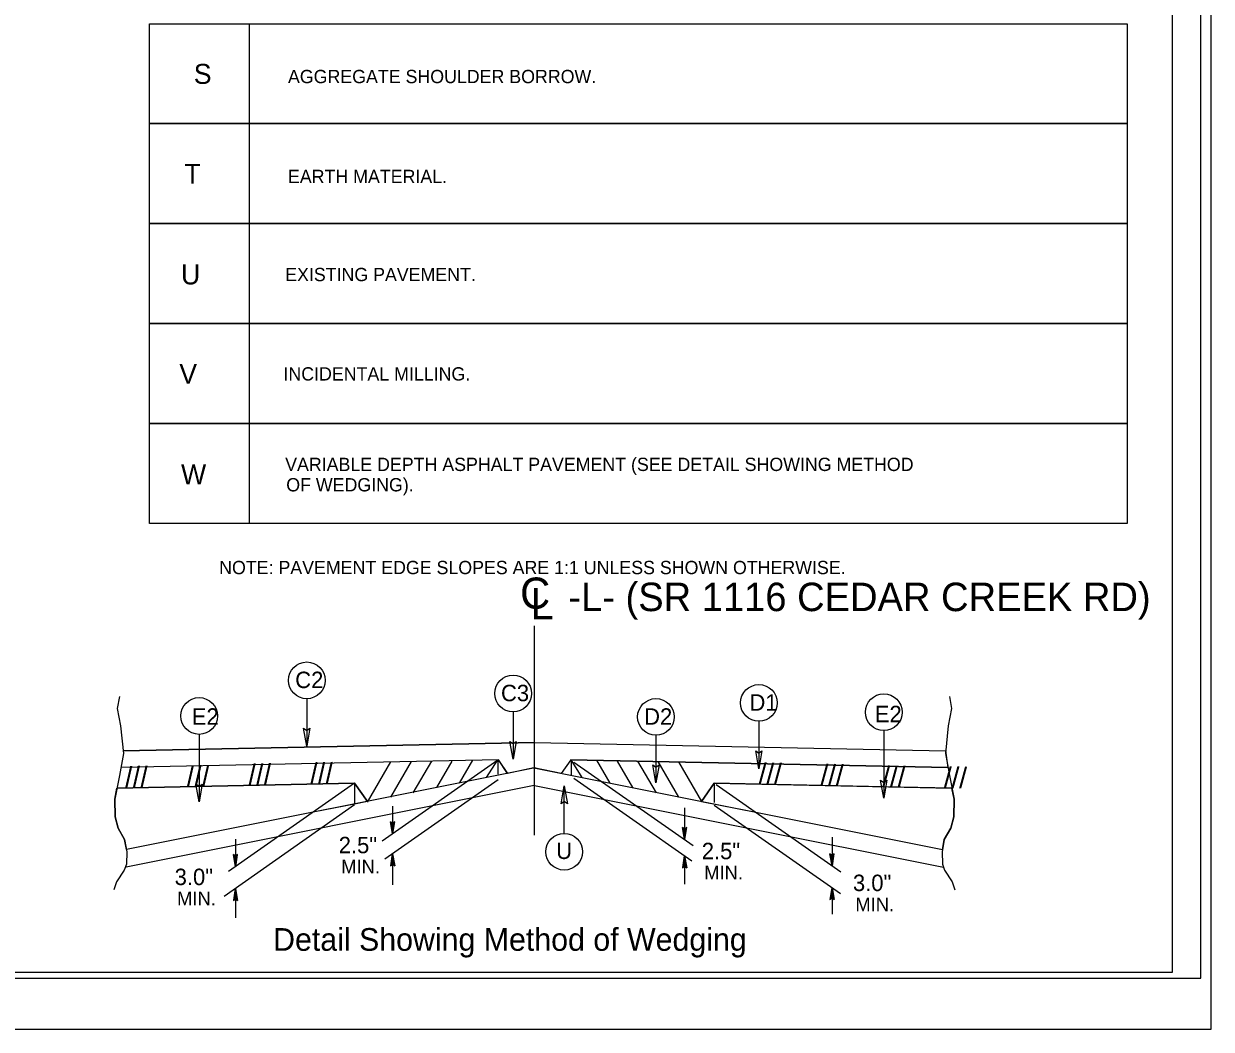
# Model space of a CAD drawing. Extents: x 573732 to 574187, y -53389 to -53257.
# Drawn here: x 573921.8 to 573984.3, y -53388.9 to -53336 of the extents above; entities that cross this region are included whole.
import ezdxf

# ---------------------------------------------------------------- set-up
doc = ezdxf.new("R2010")
doc.units = 0
for name, color, linetype in [('Old_Level_1', 7, 'Continuous'), ('Old_Level_19', 7, 'Continuous'), ('Old_Level_21', 7, 'Continuous'), ('Sheet Cutting Line CELL', 7, 'Continuous'), ('Sheet Plot Border Inside CELL', 7, 'Continuous'), ('Sheet Plot Border Outside CELL', 7, 'Continuous'), ('Sheet Typical CELL', 7, 'Continuous'), ('Typical Detail Wedge2 CELL', 7, 'Continuous'), ('Typical ID Circle CELL', 7, 'Continuous'), ('Typical Terminator CELL', 7, 'Continuous'), ('Typical Text Centerline CELL', 7, 'Continuous'), ('Typical Text General CELL', 7, 'Continuous'), ('Typical Text ID Circle CELL', 7, 'Continuous')]:
    doc.layers.add(name, color=color, linetype=linetype)

# ---------------------------------------------------------------- blocks, each defined once
blk = doc.blocks.new('CENTERLINE TEXT CL')
at = {"layer": 'Typical Text Centerline CELL'}
blk.add_text('C', height=1.64, dxfattribs=at).set_placement((-0.546, -0.261))
blk.add_text('L', height=1.641, rotation=359.9469, dxfattribs=at).set_placement((-0.001, -0.821))
blk = doc.blocks.new('TERMINATOR')
at = {"layer": 'Typical Terminator CELL'}
blk.add_lwpolyline([(-0.469, 0.081), (0, 0), (-0.471, -0.083), (-0.411, 0)], close=True, dxfattribs=at)

msp = doc.modelspace()

# ---------------------------------------------------------------- linework, layer by layer
at = {"layer": 'Old_Level_1'}
for p, q in [((573928.578, -53362.324), (573928.578, -53362.324)), ((573948.672, -53378.727), (573948.672, -53367.698)), ((573948.672, -53378.727), (573948.672, -53371.194))]:
    msp.add_line(p, q, dxfattribs=at)
at = {"layer": 'Old_Level_19'}
for points in [[(573933.675, -53341.256), (573928.412, -53341.256), (573928.412, -53335.994), (573979.867, -53335.994), (573979.867, -53341.256), (573933.675, -53341.256), (573933.675, -53335.994)], [(573933.675, -53346.518), (573928.412, -53346.518), (573928.412, -53341.256), (573979.867, -53341.256), (573979.867, -53346.518), (573933.675, -53346.518), (573933.675, -53341.256)], [(573933.675, -53351.781), (573928.412, -53351.781), (573928.412, -53346.518), (573979.867, -53346.518), (573979.867, -53351.781), (573933.675, -53351.781), (573933.675, -53346.518)], [(573933.675, -53357.043), (573928.412, -53357.043), (573928.412, -53351.781), (573979.867, -53351.781), (573979.867, -53357.043), (573933.675, -53357.043), (573933.675, -53351.781)], [(573933.675, -53362.305), (573928.412, -53362.305), (573928.412, -53357.043), (573979.868, -53357.043), (573979.868, -53362.305), (573933.675, -53362.305), (573933.675, -53357.043)]]:
    msp.add_lwpolyline(points, dxfattribs=at)
at = {"layer": 'Sheet Cutting Line CELL'}
msp.add_line((573782.222, -53388.948), (573984.302, -53388.948), dxfattribs=at)
at = {"layer": 'Sheet Plot Border Inside CELL'}
msp.add_lwpolyline([(573983.762, -53259.642), (573783.782, -53259.642), (573783.782, -53386.254), (573983.762, -53386.254)], close=True, dxfattribs=at)
at = {"layer": 'Sheet Plot Border Outside CELL'}
msp.add_lwpolyline([(573984.302, -53256.948), (573782.222, -53256.948), (573782.222, -53388.948), (573984.302, -53388.948)], close=True, dxfattribs=at)
at = {"layer": 'Sheet Typical CELL'}
msp.add_lwpolyline([(573982.262, -53259.948), (573802.262, -53259.948), (573802.262, -53385.948), (573982.262, -53385.948)], close=True, dxfattribs=at)
at = {"layer": 'Typical Detail Wedge2 CELL'}
for p, q in [((573948.671, -53373.854), (573927.027, -53374.287)), ((573927.027, -53374.287), (573948.671, -53373.854)), ((573948.671, -53373.854), (573970.317, -53374.287)), ((573948.673, -53373.854), (573970.317, -53374.287)), ((573970.317, -53374.287), (573970.441, -53375.156)), ((573946.772, -53374.759), (573926.904, -53375.156)), ((573946.772, -53374.759), (573926.904, -53375.156)), ((573941.096, -53374.873), (573939.866, -53376.981)), ((573946.748, -53374.775), (573940.65, -53379.046)), ((573942.176, -53374.851), (573941.087, -53376.72)), ((573943.245, -53374.83), (573942.268, -53376.505)), ((573944.322, -53374.832), (573943.512, -53376.219)), ((573945.409, -53374.777), (573944.703, -53375.987)), ((573946.157, -53375.685), (573946.745, -53374.767)), ((573946.745, -53374.767), (573946.745, -53375.521)), ((573947.259, -53375.472), (573946.772, -53374.759)), ((573946.772, -53374.782), (573947.259, -53375.472)), ((573950.586, -53374.759), (573950.084, -53375.472)), ((573950.586, -53374.759), (573950.084, -53375.472)), ((573950.554, -53374.775), (573950.585, -53374.777)), ((573950.586, -53374.759), (573970.441, -53375.156)), ((573970.441, -53375.156), (573950.586, -53374.759)), ((573951.186, -53375.685), (573950.599, -53374.767)), ((573950.599, -53374.767), (573950.599, -53375.598)), ((573950.752, -53374.875), (573957.035, -53379.275)), ((573951.934, -53374.777), (573952.641, -53375.987)), ((573953.02, -53374.832), (573953.83, -53376.219)), ((573954.098, -53374.83), (573955.076, -53376.505)), ((573955.167, -53374.851), (573956.256, -53376.72)), ((573956.249, -53374.873), (573957.46, -53376.95)), ((573948.704, -53375.185), (573927.189, -53379.489)), ((573948.639, -53375.185), (573947.259, -53375.472)), ((573948.639, -53375.185), (573970.154, -53379.489)), ((573950.084, -53375.472), (573948.639, -53375.185)), ((573939.203, -53375.996), (573926.693, -53376.246)), ((573926.693, -53376.246), (573939.203, -53375.996)), ((573948.663, -53376.111), (573927.182, -53380.408)), ((573939.203, -53375.996), (573932.56, -53380.647)), ((573939.883, -53376.952), (573939.203, -53375.996)), ((573939.203, -53375.996), (573939.203, -53377.087)), ((573939.203, -53375.996), (573939.882, -53376.95)), ((573946.762, -53375.819), (573940.794, -53379.997)), ((573948.68, -53376.111), (573970.211, -53380.418)), ((573950.743, -53375.73), (573956.965, -53380.086)), ((573958.14, -53375.996), (573957.46, -53376.95)), ((573957.461, -53376.95), (573958.14, -53375.996)), ((573958.14, -53375.996), (573970.651, -53376.246)), ((573958.14, -53375.996), (573958.14, -53377.01)), ((573967.062, -53376.175), (573958.14, -53375.996)), ((573958.241, -53376.066), (573964.793, -53380.655)), ((573970.651, -53376.246), (573967.062, -53376.175)), ((573939.197, -53377.122), (573932.33, -53381.954)), ((573939.203, -53377.086), (573937.024, -53377.522)), ((573939.882, -53376.95), (573939.203, -53377.086)), ((573941.205, -53377.206), (573941.205, -53378.657)), ((573956.576, -53377.29), (573956.576, -53378.953)), ((573957.46, -53376.95), (573960.319, -53377.522)), ((573958.14, -53377.142), (573964.782, -53381.795)), ((573937.024, -53377.522), (573927.189, -53379.489)), ((573941.205, -53378.657), (573941.093, -53378.021)), ((573941.205, -53378.104), (573941.093, -53378.021)), ((573941.205, -53378.657), (573941.109, -53378.033)), ((573941.125, -53378.045), (573941.205, -53378.657)), ((573941.205, -53378.657), (573941.14, -53378.056)), ((573941.157, -53378.068), (573941.205, -53378.657)), ((573941.205, -53378.657), (573941.173, -53378.08)), ((573941.189, -53378.092), (573941.205, -53378.657)), ((573941.205, -53378.657), (573941.318, -53378.021)), ((573941.318, -53378.021), (573941.205, -53378.104)), ((573941.302, -53378.033), (573941.205, -53378.657)), ((573941.205, -53378.657), (573941.284, -53378.045)), ((573941.269, -53378.056), (573941.205, -53378.657)), ((573941.205, -53378.657), (573941.253, -53378.068)), ((573941.237, -53378.08), (573941.205, -53378.657)), ((573941.205, -53378.657), (573941.221, -53378.092)), ((573941.205, -53378.104), (573941.205, -53378.657)), ((573960.319, -53377.522), (573970.154, -53379.489)), ((573956.576, -53378.953), (573956.463, -53378.316)), ((573956.576, -53378.399), (573956.463, -53378.316)), ((573956.576, -53378.953), (573956.479, -53378.328)), ((573956.495, -53378.34), (573956.576, -53378.953)), ((573956.576, -53378.953), (573956.511, -53378.352)), ((573956.527, -53378.364), (573956.576, -53378.953)), ((573956.576, -53378.953), (573956.543, -53378.375)), ((573956.559, -53378.387), (573956.576, -53378.953)), ((573956.576, -53378.953), (573956.688, -53378.316)), ((573956.688, -53378.316), (573956.576, -53378.399)), ((573956.671, -53378.328), (573956.576, -53378.953)), ((573956.576, -53378.953), (573956.655, -53378.34)), ((573956.639, -53378.352), (573956.576, -53378.953)), ((573956.576, -53378.953), (573956.623, -53378.364)), ((573956.607, -53378.375), (573956.576, -53378.953)), ((573956.576, -53378.953), (573956.591, -53378.387)), ((573956.576, -53378.399), (573956.576, -53378.953)), ((573932.934, -53378.94), (573932.934, -53380.386)), ((573964.342, -53378.835), (573964.342, -53380.339)), ((573932.934, -53380.386), (573932.821, -53379.75)), ((573932.934, -53379.832), (573932.821, -53379.75)), ((573932.934, -53380.386), (573932.837, -53379.761)), ((573932.855, -53379.774), (573932.934, -53380.386)), ((573932.934, -53380.386), (573932.871, -53379.785)), ((573932.887, -53379.796), (573932.934, -53380.386)), ((573932.934, -53380.386), (573932.902, -53379.808)), ((573932.918, -53379.82), (573932.934, -53380.386)), ((573932.934, -53380.386), (573933.047, -53379.75)), ((573933.047, -53379.75), (573932.934, -53379.832)), ((573933.031, -53379.761), (573932.934, -53380.386)), ((573932.934, -53380.386), (573933.015, -53379.774)), ((573932.999, -53379.785), (573932.934, -53380.386)), ((573932.934, -53380.386), (573932.982, -53379.796)), ((573932.967, -53379.808), (573932.934, -53380.386)), ((573932.934, -53380.386), (573932.95, -53379.82)), ((573932.934, -53379.832), (573932.934, -53380.386)), ((573941.205, -53379.71), (573941.093, -53380.347)), ((573941.109, -53380.334), (573941.205, -53379.71)), ((573941.205, -53379.71), (573941.125, -53380.323)), ((573941.14, -53380.31), (573941.205, -53379.71)), ((573941.205, -53379.71), (573941.157, -53380.299)), ((573941.173, -53380.288), (573941.205, -53379.71)), ((573941.205, -53379.71), (573941.189, -53380.276)), ((573941.205, -53379.71), (573941.205, -53381.344)), ((573941.205, -53379.71), (573941.318, -53380.347)), ((573941.205, -53380.264), (573941.205, -53379.71)), ((573941.221, -53380.276), (573941.205, -53379.71)), ((573941.205, -53379.71), (573941.237, -53380.288)), ((573941.253, -53380.299), (573941.205, -53379.71)), ((573941.205, -53379.71), (573941.269, -53380.31)), ((573941.284, -53380.323), (573941.205, -53379.71)), ((573941.205, -53379.71), (573941.302, -53380.334)), ((573956.576, -53379.813), (573956.463, -53380.45)), ((573956.479, -53380.437), (573956.576, -53379.813)), ((573956.576, -53379.813), (573956.495, -53380.426)), ((573956.511, -53380.413), (573956.576, -53379.813)), ((573956.576, -53379.813), (573956.527, -53380.402)), ((573956.543, -53380.391), (573956.576, -53379.813)), ((573956.576, -53379.813), (573956.559, -53380.379)), ((573956.576, -53379.813), (573956.576, -53381.301)), ((573956.576, -53379.813), (573956.688, -53380.45)), ((573956.576, -53380.367), (573956.576, -53379.813)), ((573956.591, -53380.379), (573956.576, -53379.813)), ((573956.576, -53379.813), (573956.607, -53380.391)), ((573956.623, -53380.402), (573956.576, -53379.813)), ((573956.576, -53379.813), (573956.639, -53380.413)), ((573956.655, -53380.426), (573956.576, -53379.813)), ((573956.576, -53379.813), (573956.671, -53380.437)), ((573964.342, -53380.339), (573964.23, -53379.703)), ((573964.342, -53379.785), (573964.23, -53379.703)), ((573964.342, -53380.339), (573964.246, -53379.715)), ((573964.262, -53379.726), (573964.342, -53380.339)), ((573964.342, -53380.339), (573964.278, -53379.737)), ((573964.294, -53379.75), (573964.342, -53380.339)), ((573964.342, -53380.339), (573964.31, -53379.761)), ((573964.326, -53379.774), (573964.342, -53380.339)), ((573964.342, -53380.339), (573964.455, -53379.703)), ((573964.455, -53379.703), (573964.342, -53379.785)), ((573964.438, -53379.715), (573964.342, -53380.339)), ((573964.342, -53380.339), (573964.422, -53379.726)), ((573964.406, -53379.737), (573964.342, -53380.339)), ((573964.342, -53380.339), (573964.39, -53379.75)), ((573964.374, -53379.761), (573964.342, -53380.339)), ((573964.342, -53380.339), (573964.358, -53379.774)), ((573964.342, -53379.785), (573964.342, -53380.339)), ((573941.093, -53380.347), (573941.205, -53380.264)), ((573941.205, -53380.264), (573941.318, -53380.347)), ((573956.463, -53380.45), (573956.576, -53380.367)), ((573956.576, -53380.367), (573956.688, -53380.45)), ((573932.934, -53381.531), (573932.821, -53382.167)), ((573932.839, -53382.155), (573932.934, -53381.531)), ((573932.934, -53381.531), (573932.855, -53382.143)), ((573932.871, -53382.131), (573932.934, -53381.531)), ((573932.934, -53381.531), (573932.887, -53382.119)), ((573932.902, -53382.108), (573932.934, -53381.531)), ((573932.934, -53381.531), (573932.918, -53382.097)), ((573932.934, -53381.531), (573932.934, -53383.077)), ((573932.934, -53381.531), (573933.047, -53382.167)), ((573932.934, -53382.084), (573932.934, -53381.531)), ((573932.95, -53382.097), (573932.934, -53381.531)), ((573932.934, -53381.531), (573932.967, -53382.108)), ((573932.983, -53382.119), (573932.934, -53381.531)), ((573932.934, -53381.531), (573932.999, -53382.131)), ((573933.015, -53382.143), (573932.934, -53381.531)), ((573932.934, -53381.531), (573933.031, -53382.155)), ((573964.342, -53381.486), (573964.23, -53382.123)), ((573964.246, -53382.111), (573964.342, -53381.486)), ((573964.342, -53381.486), (573964.262, -53382.099)), ((573964.278, -53382.087), (573964.342, -53381.486)), ((573964.342, -53381.486), (573964.294, -53382.075)), ((573964.31, -53382.063), (573964.342, -53381.486)), ((573964.342, -53381.486), (573964.326, -53382.052)), ((573964.342, -53381.486), (573964.342, -53382.883)), ((573964.342, -53381.486), (573964.455, -53382.123)), ((573964.342, -53382.039), (573964.342, -53381.486)), ((573964.358, -53382.052), (573964.342, -53381.486)), ((573964.342, -53381.486), (573964.374, -53382.063)), ((573964.39, -53382.075), (573964.342, -53381.486)), ((573964.342, -53381.486), (573964.406, -53382.087)), ((573964.422, -53382.099), (573964.342, -53381.486)), ((573964.342, -53381.486), (573964.438, -53382.111)), ((573932.821, -53382.167), (573932.934, -53382.084)), ((573932.934, -53382.084), (573933.047, -53382.167)), ((573964.23, -53382.123), (573964.342, -53382.039)), ((573964.342, -53382.039), (573964.455, -53382.123))]:
    msp.add_line(p, q, dxfattribs=at)
for points in [[(573926.826, -53371.43), (573926.71, -53372.064), (573926.884, -53372.966), (573927.037, -53374.425), (573926.826, -53375.577), (573926.577, -53376.825), (573926.596, -53377.766), (573926.749, -53378.361), (573927.095, -53378.957), (573927.21, -53379.609), (573927.191, -53380.261), (573927.076, -53380.569), (573926.673, -53381.184), (573926.538, -53381.606)], [(573970.517, -53371.43), (573970.633, -53372.064), (573970.46, -53372.966), (573970.306, -53374.425), (573970.517, -53375.577), (573970.767, -53376.825), (573970.748, -53377.766), (573970.594, -53378.361), (573970.248, -53378.957), (573970.134, -53379.609), (573970.152, -53380.261), (573970.267, -53380.569), (573970.67, -53381.184), (573970.804, -53381.606)], [(573927.189, -53379.489), (573927.095, -53378.957), (573926.749, -53378.361), (573926.596, -53377.766), (573926.577, -53376.825), (573926.692, -53376.246)], [(573970.154, -53379.489), (573970.248, -53378.957), (573970.594, -53378.361), (573970.748, -53377.766), (573970.767, -53376.825), (573970.651, -53376.246)]]:
    msp.add_lwpolyline(points, dxfattribs=at)
at = {"layer": 'Typical ID Circle CELL'}
for p, q in [((573936.687, -53371.54), (573936.687, -53374.038)), ((573947.548, -53372.23), (573947.548, -53374.728)), ((573960.489, -53372.729), (573960.489, -53375.227)), ((573931.021, -53373.417), (573931.021, -53376.97)), ((573955.068, -53373.468), (573955.068, -53375.966)), ((573967.062, -53373.219), (573967.062, -53376.772)), ((573950.238, -53378.631), (573950.238, -53376.133))]:
    msp.add_line(p, q, dxfattribs=at)
for centre in [(573936.687, -53370.573), (573947.548, -53371.263), (573960.489, -53371.762), (573931.02, -53372.45), (573955.069, -53372.501), (573967.062, -53372.252), (573950.238, -53379.598)]:
    msp.add_circle(centre, 0.967, dxfattribs=at)

# ---------------------------------------------------------------- block references
at = {"layer": 'Typical Terminator CELL', "xscale": 2, "yscale": 2}
for p, rotation in [((573936.687, -53374.038), -90), ((573936.687, -53374.038), -90), ((573947.548, -53374.728), -90), ((573947.548, -53374.728), -90), ((573960.489, -53375.227), -90), ((573960.489, -53375.227), -90), ((573955.068, -53375.966), -90), ((573955.068, -53375.966), -90), ((573931.021, -53376.97), -90), ((573931.021, -53376.97), -90), ((573950.238, -53376.133), 90), ((573950.238, -53376.133), 90), ((573967.062, -53376.772), -90)]:
    msp.add_blockref('TERMINATOR', p, dxfattribs=dict(at, rotation=rotation))
at = {"layer": 'Typical Text Centerline CELL'}
msp.add_blockref('CENTERLINE TEXT CL', (573948.463, -53366.538), dxfattribs=at)

# ---------------------------------------------------------------- texts
at = {"layer": 'Old_Level_21'}
for s, height, p in [('S', 1.051, (573930.737, -53339.16)), ('AGGREGATE SHOULDER BORROW.', 0.70001, (573935.697, -53339.123)), ('T ', 1.0505, (573930.238, -53344.423)), ('EARTH MATERIAL.', 0.70001, (573935.697, -53344.385)), ('U ', 1.0505, (573930.066, -53349.722)), ('EXISTING PAVEMENT.', 0.70001, (573935.55, -53349.55)), ('V ', 1.0505, (573929.976, -53354.956)), ('INCIDENTAL MILLING.', 0.70001, (573935.46, -53354.783)), ('W ', 1.0505, (573930.066, -53360.247)), ('VARIABLE DEPTH ASPHALT PAVEMENT (SEE DETAIL SHOWING METHOD', 0.7, (573935.55, -53359.549)), ('OF WEDGING).', 0.7, (573935.607, -53360.623)), ('NOTE: PAVEMENT EDGE SLOPES ARE 1:1 UNLESS SHOWN OTHERWISE.', 0.70001, (573932.075, -53364.981))]:
    msp.add_text(s, height=height, dxfattribs=at).set_placement(p)
at = {"layer": 'Typical Detail Wedge2 CELL'}
for height, rotation, p in [(1.085, 1.14453, (573933.619, -53376.098)), (1.085, 1.14629, (573936.873, -53376.031)), (1.085, 358.85527, (573960.471, -53376.031)), (1.085, 358.85361, (573963.725, -53376.098)), (1.0854, 1.14473, (573927.123, -53376.231)), (1.0854, 1.14639, (573930.367, -53376.193)), (1.0854, 358.85537, (573966.975, -53376.193)), (1.0854, 358.85371, (573970.22, -53376.231))]:
    msp.add_text('/// ', height=height, rotation=rotation, dxfattribs=at).set_placement(p)
for s, height, p in [('2.5"', 0.8653, (573938.37, -53379.68)), ('2.5"', 0.8653, (573957.482, -53379.994)), ('3.0"', 0.8653, (573929.732, -53381.356)), ('MIN.', 0.7231, (573938.498, -53380.744)), ('MIN.', 0.7231, (573957.608, -53381.058)), ('3.0"', 0.8653, (573965.44, -53381.671)), ('MIN.', 0.7231, (573929.859, -53382.42)), ('MIN.', 0.7231, (573965.567, -53382.735))]:
    msp.add_text(s, height=height, dxfattribs=at).set_placement(p)
at = {"layer": 'Typical Text Centerline CELL'}
msp.add_text('-L- (SR 1116 CEDAR CREEK RD)', height=1.5, rotation=360, dxfattribs=at).set_placement((573950.459, -53366.928))
at = {"layer": 'Typical Text General CELL'}
msp.add_text('Detail Showing Method of Wedging', height=1.19356, dxfattribs=at).set_placement((573934.915, -53384.815))
at = {"layer": 'Typical Text ID Circle CELL'}
for s, height, p in [('C2', 0.8653, (573936.078, -53370.981)), ('C3', 0.8653, (573946.911, -53371.672)), ('D1', 0.8653, (573959.992, -53372.171)), ('E2', 0.8653, (573930.632, -53372.911)), ('D2', 0.8653, (573954.447, -53372.91)), ('E2', 0.8653, (573966.592, -53372.779)), ('U', 0.865, (573949.815, -53379.981))]:
    msp.add_text(s, height=height, dxfattribs=at).set_placement(p)

doc.saveas('drawing.dxf')
